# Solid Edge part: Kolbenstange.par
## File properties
Dokumentum tartalom típus: 0
Last saved by: bmolnar
Revision: 79
Sűrűség: 0,000 kg/m^3
Pontosság: 0,990
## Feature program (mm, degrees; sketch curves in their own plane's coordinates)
base feature "unnamed BaseFeature 1"
sketch for "unnamed Protrusion 1" plane through (18, 0.0012, 0) normal (1, 0, 0) x-axis (0, 1, 0)
  circle centre (-0.0012, 0) radius 6
extrude "unnamed Protrusion 1" add finite 16.45 along -normal
sketch for "Furat_1" plane through (-10, 0, 0) normal (-1, 0, 0) x-axis (0, -1, 0)
  hole centre (0, 0) bore radius 1.2295
hole "Furat_1" nominal diameter 3 finite  VBottomAngle = 118 deg; ThreadDepth = 7 mm
chamfer "Letörés_1" setback 0.3  SetBackValue2 = 45 deg
sketch for "Kihúzás_2" plane through (18, 0.0012, 0) normal (1, 0, 0) x-axis (0, 1, 0)
extrude "Kihúzás_2" add finite 4.7 along +normal
sketch used by "Kihúzás_3" plane through (22.7, 0, 0) normal (1, 0, 0) x-axis (0, 0, -1)
extrude "Kihúzás_3" add finite 1.6 along +normal
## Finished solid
Body 1: solid body, 17 faces, 25 edges, 10 vertices.
  Faces by surface: plane 8, cylinder 5, cone 4
  Edges by curve: circle 13, line 6, spline 4, ellipse 2
Bounding box of the edges (mm): 34.300 x 12.000 x 12.000, from (-10, -6, -6) to (24.3, 6, 6).
Cylindrical faces by radius (mm): R1.2295 x2, R3 x1, R4 x1, R6 x1
Conical faces (half-angle, radius in mm at the cone's reference point): 45 deg R1.5295 x1, 45 deg R2.75 x2, 59 deg R1.2295 x1
Planar faces by outward normal: +x 2, +z 1, -x 2, -z 1, oblique 2
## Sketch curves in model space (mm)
circle centre (22.7, 0, 0) radius 4
circle centre (18, 0, 0) radius 6
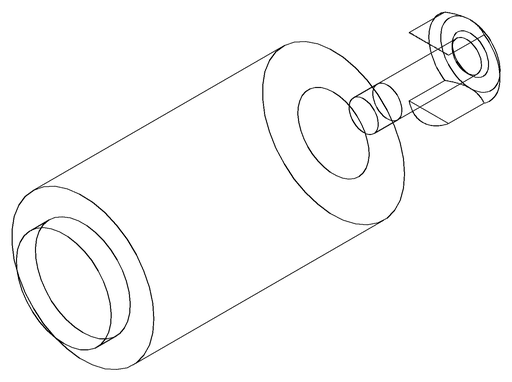
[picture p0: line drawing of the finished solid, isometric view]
